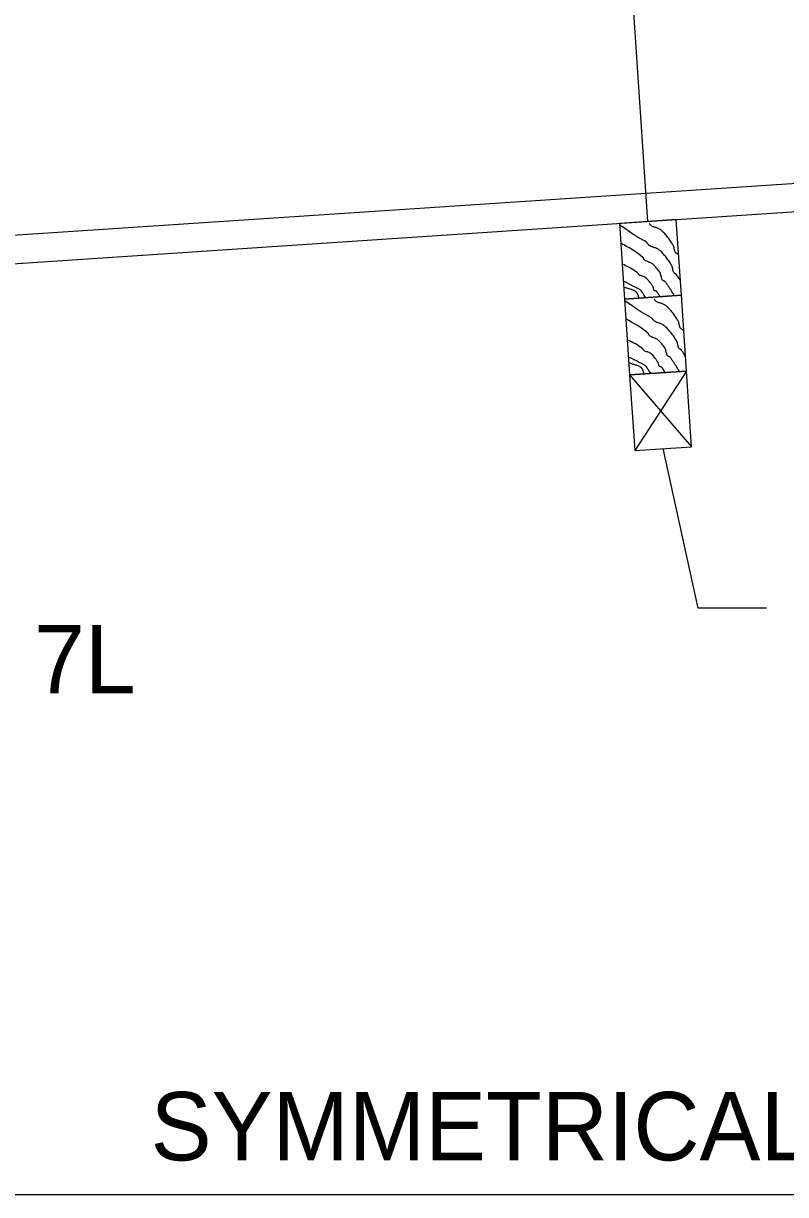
# Model space of a CAD drawing. Extents: x 1312564.2 to 1312581.5, y 1207298.4 to 1207352.6.
# Drawn here: x 1312569.216 to 1312570.104, y 1207302.284 to 1207303.65 of the extents above; entities that cross this region are included whole.
import ezdxf

# ---------------------------------------------------------------- set-up
doc = ezdxf.new("R2010")
doc.units = 0
for name, color, linetype in [('Level 13', 7, 'Continuous'), ('Level 14', 7, 'Continuous'), ('Level 15', 7, 'Continuous'), ('Level 20', 7, 'Continuous')]:
    doc.layers.add(name, color=color, linetype=linetype)

msp = doc.modelspace()

# ---------------------------------------------------------------- linework, layer by layer
at = {"layer": 'Level 13'}
for points in [[(1312569.9817166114, 1207303.350201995), (1312569.977304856, 1207303.3566756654), (1312569.9766446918, 1207303.3573409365), (1312569.9758324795, 1207303.357865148), (1312569.9750146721, 1207303.3583838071), (1312569.9743377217, 1207303.3590324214), (1312569.973777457, 1207303.3599762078), (1312569.973377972, 1207303.3610026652), (1312569.9728615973, 1207303.3632053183), (1312569.972389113, 1207303.3654438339), (1312569.9718232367, 1207303.3670280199), (1312569.9715610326, 1207303.3675216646), (1312569.9685009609, 1207303.372409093), (1312569.9651335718, 1207303.3770724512), (1312569.9613758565, 1207303.3814431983), (1312569.9593246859, 1207303.3834974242), (1312569.9582514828, 1207303.384488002), (1312569.9571448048, 1207303.3854527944), (1312569.9557341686, 1207303.3864613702), (1312569.9542049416, 1207303.3872655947), (1312569.9509551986, 1207303.3885226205), (1312569.947724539, 1207303.3897471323), (1312569.9455119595, 1207303.3909589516), (1312569.9448419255, 1207303.3914623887), (1312569.9441235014, 1207303.3922240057), (1312569.9434977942, 1207303.393100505), (1312569.9428522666, 1207303.3939566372), (1312569.9420743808, 1207303.394657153), (1312569.9383507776, 1207303.3969405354), (1312569.93454223, 1207303.3991021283), (1312569.9307431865, 1207303.4012830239), (1312569.927048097, 1207303.4036243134), (1312569.9114102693, 1207303.4143126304)], [(1312569.9797852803, 1207303.3791722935), (1312569.979066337, 1207303.380221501), (1312569.9787644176, 1207303.3805804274), (1312569.978406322, 1207303.3808871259), (1312569.9775945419, 1207303.3814115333), (1312569.9767768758, 1207303.3819301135), (1312569.9764114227, 1207303.3822295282), (1312569.9760992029, 1207303.3825782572), (1312569.9755377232, 1207303.3835214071), (1312569.9751376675, 1207303.3845475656), (1312569.9746214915, 1207303.3867503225), (1312569.974149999, 1207303.3889893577), (1312569.9738057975, 1207303.390060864), (1312569.9733225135, 1207303.3910675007), (1312569.9725810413, 1207303.3923060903), (1312569.971822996, 1207303.3935329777), (1312569.9668702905, 1207303.400600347), (1312569.96310948, 1207303.4049688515), (1312569.961067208, 1207303.4070295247), (1312569.9600020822, 1207303.4080259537), (1312569.9589062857, 1207303.4089986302), (1312569.9574847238, 1207303.4099883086), (1312569.9559068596, 1207303.410730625), (1312569.9525283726, 1207303.4118316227), (1312569.9492631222, 1207303.4130185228), (1312569.947826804, 1207303.4138682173), (1312569.9466034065, 1207303.4150082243), (1312569.9454094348, 1207303.4165119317)], [(1312569.9749230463, 1207303.3322077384), (1312569.9718331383, 1207303.3371453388), (1312569.9699675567, 1207303.3400496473), (1312569.9680439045, 1207303.3429175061), (1312569.966080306, 1207303.3457566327), (1312569.9640948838, 1207303.3485747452), (1312569.96378966, 1207303.348899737), (1312569.9634142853, 1207303.3491496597), (1312569.962544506, 1207303.3495220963), (1312569.9616683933, 1207303.349887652), (1312569.9609687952, 1207303.350441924), (1312569.9606273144, 1207303.3509371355), (1312569.9603375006, 1207303.3514612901), (1312569.9598845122, 1207303.352580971), (1312569.9592865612, 1207303.3549976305), (1312569.9587211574, 1207303.3574446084), (1312569.9580454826, 1207303.3591509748), (1312569.9577345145, 1207303.3596746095), (1312569.9559913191, 1207303.362157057), (1312569.9540993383, 1207303.364532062), (1312569.9520472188, 1207303.3667783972), (1312569.9498236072, 1207303.3688748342), (1312569.9486746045, 1207303.3697177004), (1312569.947417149, 1207303.370397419), (1312569.9447289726, 1207303.3714823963), (1312569.9420632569, 1207303.3725597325), (1312569.9408338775, 1207303.3732298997), (1312569.939724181, 1207303.374059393), (1312569.9393020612, 1207303.3746477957), (1312569.939009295, 1207303.375358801), (1312569.938696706, 1207303.376049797), (1312569.9382151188, 1207303.3765781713), (1312569.9122098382, 1207303.3934498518)], [(1312569.9580907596, 1207303.3310855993), (1312569.9537406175, 1207303.337360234), (1312569.95350682, 1207303.3375794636), (1312569.953203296, 1207303.3377056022), (1312569.9524783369, 1207303.3378009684), (1312569.951748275, 1207303.337891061), (1312569.9511956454, 1207303.3382206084), (1312569.9510386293, 1207303.338454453), (1312569.950908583, 1207303.3387024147), (1312569.9507147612, 1207303.3392331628), (1312569.9504897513, 1207303.340381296), (1312569.950286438, 1207303.3415446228), (1312569.9501197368, 1207303.3420943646), (1312569.9498706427, 1207303.3426027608), (1312569.9489777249, 1207303.3440191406), (1312569.948057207, 1207303.345423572), (1312569.946095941, 1207303.3481601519), (1312569.942713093, 1207303.3519476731), (1312569.9420828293, 1207303.3525272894), (1312569.9414304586, 1207303.3530891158), (1312569.9405207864, 1207303.3537181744), (1312569.9395314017, 1207303.3542034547), (1312569.9374246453, 1207303.3549270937), (1312569.935332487, 1207303.355628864), (1312569.9339066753, 1207303.3563627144), (1312569.93368858, 1207303.3565149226), (1312569.9334772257, 1207303.356677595), (1312569.9329033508, 1207303.3572983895), (1312569.932412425, 1207303.3580231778), (1312569.93189975, 1207303.3587237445), (1312569.9312606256, 1207303.3592718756), (1312569.915477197, 1207303.3684598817)], [(1312569.9412986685, 1207303.3299661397), (1312569.9397506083, 1207303.3322024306), (1312569.939406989, 1207303.3327146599), (1312569.9390717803, 1207303.33324093), (1312569.93707211, 1207303.336469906), (1312569.9355338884, 1207303.338397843), (1312569.9336115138, 1207303.3398480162), (1312569.927237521, 1207303.3431447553), (1312569.9166275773, 1207303.3486324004)], [(1312569.933343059, 1207303.329435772), (1312569.9329592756, 1207303.331189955), (1312569.9325335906, 1207303.3329056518), (1312569.931946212, 1207303.3344728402), (1312569.9315544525, 1207303.3351663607), (1312569.9313275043, 1207303.3354845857), (1312569.9312054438, 1207303.3356358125), (1312569.931142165, 1207303.3357093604), (1312569.9311099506, 1207303.3357456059), (1312569.9310936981, 1207303.3357635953), (1312569.9310773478, 1207303.335781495), (1312569.9307736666, 1207303.336094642), (1312569.9304531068, 1207303.3363922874), (1312569.9297646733, 1207303.3369441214), (1312569.9282217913, 1207303.3378953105), (1312569.924657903, 1207303.339358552), (1312569.920810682, 1207303.3405615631), (1312569.9189136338, 1207303.3411874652), (1312569.9171051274, 1207303.3418946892)], [(1312569.9876019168, 1207303.2619213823), (1312569.9831901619, 1207303.2683950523), (1312569.9825299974, 1207303.2690603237), (1312569.9817177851, 1207303.2695845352), (1312569.9808999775, 1207303.270103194), (1312569.9802230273, 1207303.2707518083), (1312569.9796627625, 1207303.271695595), (1312569.9792632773, 1207303.2727220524), (1312569.9787469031, 1207303.2749247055), (1312569.9782744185, 1207303.2771632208), (1312569.977708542, 1207303.2787474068), (1312569.9774463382, 1207303.2792410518), (1312569.9743862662, 1207303.2841284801), (1312569.9710188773, 1207303.288791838), (1312569.9672611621, 1207303.2931625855), (1312569.9652099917, 1207303.2952168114), (1312569.9641367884, 1207303.2962073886), (1312569.9630301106, 1207303.2971721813), (1312569.961619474, 1207303.298180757), (1312569.960090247, 1207303.2989849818), (1312569.9568405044, 1207303.3002420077), (1312569.9536098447, 1207303.3014665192), (1312569.9513972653, 1207303.3026783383), (1312569.9507272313, 1207303.3031817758), (1312569.950008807, 1207303.3039433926), (1312569.9493831, 1207303.3048198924), (1312569.9487375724, 1207303.3056760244), (1312569.9479596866, 1207303.3063765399), (1312569.9442360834, 1207303.3086599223), (1312569.940427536, 1207303.3108215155), (1312569.9366284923, 1207303.3130024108), (1312569.9329334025, 1207303.3153437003), (1312569.917295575, 1207303.3260320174)], [(1312569.9856705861, 1207303.2908916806), (1312569.9849516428, 1207303.2919408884), (1312569.9846497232, 1207303.2922998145), (1312569.9842916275, 1207303.2926065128), (1312569.9834798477, 1207303.29313092), (1312569.9826621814, 1207303.293649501), (1312569.9822967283, 1207303.2939489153), (1312569.9819845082, 1207303.2942976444), (1312569.9814230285, 1207303.2952407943), (1312569.9810229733, 1207303.2962669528), (1312569.9805067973, 1207303.29846971), (1312569.9800353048, 1207303.3007087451), (1312569.979691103, 1207303.301780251), (1312569.979207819, 1207303.3027868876), (1312569.978466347, 1207303.3040254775), (1312569.9777083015, 1207303.3052523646), (1312569.9727555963, 1207303.312319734), (1312569.9689947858, 1207303.3166882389), (1312569.966952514, 1207303.3187489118), (1312569.9658873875, 1207303.3197453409), (1312569.9647915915, 1207303.3207180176), (1312569.9633700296, 1207303.3217076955), (1312569.961792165, 1207303.3224500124), (1312569.958413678, 1207303.32355101), (1312569.9551484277, 1207303.3247379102), (1312569.9537121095, 1207303.3255876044), (1312569.9524887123, 1207303.3267276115), (1312569.9512947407, 1207303.3282313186)], [(1312569.9808083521, 1207303.2439271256), (1312569.977718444, 1207303.248864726), (1312569.9758528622, 1207303.251769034), (1312569.9739292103, 1207303.2546368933), (1312569.971965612, 1207303.2574760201), (1312569.9699801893, 1207303.2602941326), (1312569.9696749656, 1207303.2606191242), (1312569.969299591, 1207303.260869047), (1312569.9684298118, 1207303.2612414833), (1312569.9675536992, 1207303.261607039), (1312569.9668541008, 1207303.2621613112), (1312569.96651262, 1207303.2626565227), (1312569.9662228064, 1207303.2631806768), (1312569.965769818, 1207303.2643003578), (1312569.965171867, 1207303.2667170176), (1312569.9646064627, 1207303.2691639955), (1312569.9639307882, 1207303.2708703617), (1312569.9636198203, 1207303.2713939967), (1312569.9618766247, 1207303.2738764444), (1312569.9599846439, 1207303.2762514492), (1312569.9579325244, 1207303.2784977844), (1312569.955708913, 1207303.280594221), (1312569.9545599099, 1207303.2814370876), (1312569.953302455, 1207303.2821168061), (1312569.9506142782, 1207303.2832017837), (1312569.9479485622, 1207303.2842791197), (1312569.9467191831, 1207303.2849492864), (1312569.945609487, 1207303.2857787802), (1312569.945187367, 1207303.2863671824), (1312569.9448946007, 1207303.2870781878), (1312569.9445820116, 1207303.287769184), (1312569.9441004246, 1207303.288297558), (1312569.9180951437, 1207303.305169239)], [(1312569.9639760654, 1207303.2428049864), (1312569.959625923, 1207303.2490796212), (1312569.9593921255, 1207303.2492988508), (1312569.9590886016, 1207303.2494249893), (1312569.9583636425, 1207303.2495203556), (1312569.9576335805, 1207303.249610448), (1312569.957080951, 1207303.2499399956), (1312569.956923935, 1207303.25017384), (1312569.9567938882, 1207303.2504218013), (1312569.9566000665, 1207303.25095255), (1312569.956375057, 1207303.2521006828), (1312569.9561717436, 1207303.2532640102), (1312569.9560050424, 1207303.2538137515), (1312569.9557559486, 1207303.2543221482), (1312569.9548630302, 1207303.2557385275), (1312569.9539425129, 1207303.2571429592), (1312569.9519812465, 1207303.259879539), (1312569.9485983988, 1207303.2636670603), (1312569.947968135, 1207303.2642466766), (1312569.9473157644, 1207303.2648085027), (1312569.946406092, 1207303.2654375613), (1312569.9454167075, 1207303.2659228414), (1312569.943309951, 1207303.266646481), (1312569.941217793, 1207303.267348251), (1312569.939791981, 1207303.2680821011), (1312569.9395738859, 1207303.2682343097), (1312569.9393625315, 1207303.2683969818), (1312569.9387886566, 1207303.269017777), (1312569.9382977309, 1207303.269742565), (1312569.9377850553, 1207303.270443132), (1312569.937145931, 1207303.2709912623), (1312569.9213625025, 1207303.2801792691)], [(1312569.9471839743, 1207303.241685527), (1312569.945635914, 1207303.2439218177), (1312569.9452922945, 1207303.244434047), (1312569.9449570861, 1207303.244960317), (1312569.9429574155, 1207303.2481892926), (1312569.9414191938, 1207303.2501172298), (1312569.9394968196, 1207303.2515674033), (1312569.9331228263, 1207303.254864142), (1312569.922512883, 1207303.260351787)], [(1312569.9392283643, 1207303.2411551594), (1312569.9388445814, 1207303.242909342), (1312569.9384188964, 1207303.2446250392), (1312569.9378315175, 1207303.2461922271), (1312569.9374397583, 1207303.2468857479), (1312569.93721281, 1207303.247203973), (1312569.9370907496, 1207303.2473551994), (1312569.937027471, 1207303.2474287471), (1312569.936995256, 1207303.247464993), (1312569.9369790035, 1207303.2474829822), (1312569.9369626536, 1207303.2475008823), (1312569.9366589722, 1207303.2478140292), (1312569.9363384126, 1207303.2481116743), (1312569.9356499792, 1207303.2486635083), (1312569.9341070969, 1207303.2496146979), (1312569.9305432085, 1207303.2510779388), (1312569.9266959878, 1207303.2522809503), (1312569.9247989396, 1207303.2529068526), (1312569.9229904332, 1207303.2536140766)]]:
    msp.add_spline(points, degree=3, dxfattribs=at)
at = {"layer": 'Level 14'}
for p, q in [((1312569.9225887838, 1207303.2400458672), (1312569.9946514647, 1207303.156177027)), ((1312569.9887661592, 1207303.2444576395), (1312569.9284740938, 1207303.151765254))]:
    msp.add_line(p, q, dxfattribs=at)
at = {"layer": 'Level 15'}
for p, q in [((1312569.9439068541, 1207303.4188129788), (1312569.915425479, 1207303.8460388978)), ((1312568.2091764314, 1207303.3364014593), (1312575.5205605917, 1207303.8238210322)), ((1312568.2113823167, 1207303.3033127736), (1312575.5205605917, 1207303.7905852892)), ((1312570.0023635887, 1207302.9680317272), (1312569.9615627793, 1207303.1539711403)), ((1312570.082092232, 1207302.9680317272), (1312570.0023635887, 1207302.9680317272)), ((1312565.7291221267, 1207302.2843292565), (1312575.5205605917, 1207302.2843292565))]:
    msp.add_line(p, q, dxfattribs=at)
for points in [[(1312569.9769955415, 1207303.421018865), (1312569.9108181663, 1207303.4166070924), (1312569.916703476, 1207303.3283264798), (1312569.9828808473, 1207303.3327382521)], [(1312569.9828808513, 1207303.3327382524), (1312569.916703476, 1207303.3283264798), (1312569.922588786, 1207303.2400458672), (1312569.988766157, 1207303.2444576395)], [(1312569.9887661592, 1207303.2444576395), (1312569.9225887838, 1207303.2400458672), (1312569.9284740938, 1207303.151765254), (1312569.9946514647, 1207303.156177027)]]:
    msp.add_lwpolyline(points, close=True, dxfattribs=at)

# ---------------------------------------------------------------- texts
at = {"layer": 'Level 20'}
for s, p in [('7L', (1312569.2283571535, 1207302.8685948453)), ('SYMMETRICAL ABOUT BULLNOSE CENTERLINE', (1312569.364287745, 1207302.3241935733))]:
    msp.add_text(s, height=0.07972865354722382, dxfattribs=at).set_placement(p)

doc.saveas('drawing.dxf')
